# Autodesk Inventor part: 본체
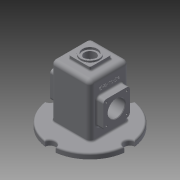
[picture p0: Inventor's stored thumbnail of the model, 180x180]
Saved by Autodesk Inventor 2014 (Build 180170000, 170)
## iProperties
Created: 2018-07
Part Number: 본체
Material: Generic
Document SubType Name: Modeling
Designer: kh
Density: 1 g/cm^3
Appearance: Default
Author: kh
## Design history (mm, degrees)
sketch "Sketch1"
  geometry: L1 (-75, 0)-(75, 0); L2 (0, -75)-(0, 75); C1 r 10 at (75, 0); C2 r 10 at (0, 75); C3 r 10 at (-75, 0); C4 r 10 at (0, -75); A1 r 75 centre (0, 0) between (-75, 0) and (75, 0); 1 further point
  constraints: 5 centre point, 5 coincident, 4 end point, 4 point on circle, 1 horizontal, 1 perpendicular
  dimensions: "d0" = 150 diameter of A1; "d2" = 150 distance of L1.start L1.end; "d3" = 150 distance of L2.start L2.end; "d4" = 20 diameter of C1; "d5" = 20 diameter of C2; "d6" = 20 diameter of C3; "d7" = 20 diameter of C4
extrude "Extrusion1" new body sketch "Sketch1" distance "d8" = 10; taper "d9" = 0 deg
extrude "Extrusion2" cut sketch "Sketch1" distance "d10" = 10; taper "d11" = 0 deg
sketch "Sketch2"
  geometry: L1 (-37, -37)-(37, -37); L2 (37, -37)-(37, 37); L3 (37, 37)-(-37, 37); L4 (-37, 37)-(-37, -37); L5 (-37, -37)-(37, 37); L6 (37, -37)-(-37, 37); 1 further point
  constraints: 12 end point, 2 midpoint, 2 parallel, 1 horizontal, 1 perpendicular
  dimensions: "d12" = 74 distance of L3.end L2.end; "d13" = 74 distance of L2.end L1.end
extrude "Extrusion3" join sketch "Sketch2" distance "d14" = 100; taper "d15" = 0 deg
sketch "Sketch3"
  geometry: L1 (-37, -37)-(37, -37) reference; L2 (37, -37)-(37, 37) reference; L3 (37, 37)-(-37, 37) reference; L4 (-37, 37)-(-37, -37) reference; L5 (-20, -20)-(20, -20); L6 (20, -20)-(20, 20); L7 (20, 20)-(-20, 20); L8 (-20, 20)-(-20, -20); L9 (-20, -20)-(20, 20); L10 (20, -20)-(-20, 20); 1 further point
  constraints: 12 end point, 2 midpoint, 2 parallel, 1 horizontal, 1 perpendicular
  dimensions: "d16" = 40 distance of L7.end L6.end; "d17" = 40 distance of L6.end L5.end
extrude "Extrusion4" join sketch "Sketch3" distance "d18" = 7; taper "d19" = 0 deg
sketch "Sketch4"
  geometry: L1 (-20, -20)-(20, -20) reference; L2 (20, -20)-(20, 20) reference; L3 (20, 20)-(-20, 20) reference; L4 (-20, 20)-(-20, -20) reference; C1 r 17.5 at (0, 0); 1 further point
  constraints: 1 centre point, 1 coincident
  dimensions: "d20" = 35 diameter of C1
extrude "Extrusion5" join sketch "Sketch4" distance "d21" = 3; taper "d22" = 0 deg
sketch "Sketch5"
  geometry: L1 (65, 10)-(65, 0) reference; L2 (65, 0)-(-65, 0) reference; L3 (-65, 0)-(-65, 10) reference; L4 (-65, 10)-(-37, 10) reference; L5 (-37, 10)-(-37, 110) reference; L6 (-37, 110)-(-20, 110) reference; L7 (-20, 110)-(-20, 117) reference; L8 (-20, 117)-(-17.5, 117) reference; L9 (-17.5, 117)-(-17.5, 120) reference; L10 (-17.5, 120)-(17.5, 120) reference; L11 (17.5, 120)-(17.5, 117) reference; L12 (17.5, 117)-(20, 117) reference; L13 (20, 117)-(20, 110) reference; L14 (20, 110)-(37, 110) reference; L15 (37, 110)-(37, 10) reference; L16 (37, 10)-(65, 10) reference; L17 (-32, 105)-(32, 105); L18 (32, 105)-(32, 0); L19 (32, 0)-(-32, 0); L20 (-32, 0)-(-32, 105)
  constraints: 8 end point, 2 parallel, 1 horizontal, 1 perpendicular, 1 point on line
  dimensions: "d26" = 64 distance of L18.end L19.end; "d27" = 5 distance between parallel lines of L15 L18; "d29" = 5 distance between parallel lines of L17 L6
extrude "Extrusion6" cut sketch "Sketch5" stored distance "d30" = 64; taper "d31" = 0 deg
sketch "Sketch7"
  geometry: L1 (70, 62)-(20, 62); L2 (20, 62)-(20, 12); L3 (20, 12)-(70, 12); L4 (70, 12)-(70, 62); L5 (70, 37)-(20, 37); L6 (45, 12)-(45, 62); 2 further points
  constraints: 12 end point, 5 midpoint, 2 parallel, 1 horizontal, 1 horizontal alignment, 1 perpendicular
  dimensions: "d33" = 50 distance of L2.end L3.end; "d34" = 50 distance of L1.end L2.end; "d35" = 55 distance from line of point (-10, 37) L6
extrude "Extrusion7" join sketch "Sketch7" distance "d36" = 13; taper "d37" = 0 deg
mirror "Mirror1"
sketch "Sketch8"
  geometry: L1 (65, 10)-(65, 0) reference; L2 (65, 0)-(32, 0) reference; L3 (32, 0)-(32, 105) reference; L4 (32, 105)-(-32, 105) reference; L5 (-32, 105)-(-32, 0) reference; L6 (-32, 0)-(-65, 0) reference; L7 (-65, 0)-(-65, 10) reference; L8 (-65, 10)-(-37, 10) reference; L9 (-37, 10)-(-37, 30) reference; L10 (-37, 30)-(-50, 30) reference; L11 (-50, 30)-(-50, 80) reference; L12 (-50, 80)-(-37, 80) reference; L13 (-37, 80)-(-37, 110) reference; L14 (-37, 110)-(-20, 110) reference; L15 (-20, 110)-(-20, 117) reference; L16 (-20, 117)-(-17.5, 117) reference; L17 (-17.5, 117)-(-17.5, 120) reference; L18 (-17.5, 120)-(17.5, 120) reference; L19 (17.5, 120)-(17.5, 117) reference; L20 (17.5, 117)-(20, 117) reference; L21 (20, 117)-(20, 110) reference; L22 (20, 110)-(37, 110) reference; L23 (37, 110)-(37, 80) reference; L24 (37, 80)-(50, 80) reference; L25 (50, 80)-(50, 30) reference; L26 (50, 30)-(37, 30) reference; L27 (37, 30)-(37, 10) reference; L28 (37, 10)-(65, 10) reference; L29 (-32, 55)-(32, 55); L30 (-32, 30)-(-25, 32.548); L31 (-25, 32.548)-(-25, 55); L32 (-32, 30)-(-32, 55); 1 further point
  constraints: 8 end point, 4 point on line, 2 perpendicular, 1 collinear
  dimensions: "d38" = 55 vertical distance of point (0, 0) L29.end; "d39" = 7 distance between parallel lines of L32 L31; "d40" = 110 deg angle of L5 L30; "d41" = 50 diameter of L30.start L29
revolve "Revolution1" sketch "Sketch8" stored, may be unused: angle "d42" = 90 deg
mirror "Mirror2"
sketch "Sketch9"
  geometry: C1 r 16 at (25, 25); 1 further point
  constraints: 1 centre point, 1 horizontal alignment
  dimensions: "d43" = 32 diameter of C1; "d44" = 55 distance of C1.centre point (80, 25)
extrude "Extrusion8" cut sketch "Sketch9" stored distance "d45" = 13; taper "d46" = 0 deg
sketch "Sketch10"
  geometry: C1 r 17.5 at (0, 0) reference; 1 further point
hole "Hole1" sketch "Sketch10" at (0, 0) diameter "d47" = 21; stored, may be unused: countersink angle "d51" = 90 deg, drill point angle "d53" = 0 deg; dims "d48" = 6, "d49" = 28, "d50" = 4, "d52" = 8
fillet "Fillet1" dims "d54" = 8
fillet "Fillet2" dims "d55" = 3
fillet "Fillet5" dims "d58" = 6
fillet "Fillet6" dims "d59" = 6
sketch "Sketch11"
  geometry: L1 (50, 38)-(50, 0) reference; L2 (44, -6)-(6, -6) reference; L3 (0, 0)-(0, 38) reference; L4 (6, 44)-(44, 44) reference; L5 (70, -32.807)-(70, 70.807) reference; L6 (73, 74.902)-(80, 74.902) reference; L7 (80, 74.902)-(80, -36.902) reference; L8 (80, -36.902)-(73, -36.902) reference; C1 r 16 at (25, 19) reference; A1 r 6 centre (44, 38) between (50, 38) and (44, 44) reference; A2 r 6 centre (44, 0) between (44, -6) and (50, 0) reference; A3 r 6 centre (6, 0) between (0, 0) and (6, -6) reference; A4 r 6 centre (6, 38) between (6, 44) and (0, 38) reference; 1 further point
  constraints: 2 other
hole "Hole2" sketch "Sketch11" at (6, 0), (44, 0), (44, 38), (6, 38) diameter "d60" = 3.242; stored, may be unused: countersink angle "d64" = 90 deg, drill point angle "d66" = 118 deg; dims "d61" = 8, "d62" = 28, "d63" = 4, "d65" = 10
sketch "Sketch12"
  geometry: L1 (26, 62)-(64, 62) reference; L2 (70, 56)-(70, 18) reference; L3 (64, 12)-(26, 12) reference; L4 (20, 18)-(20, 56) reference; L5 (0, 88.807)-(0, -14.807) reference; L6 (-3, -18.902)-(-10, -18.902) reference; L7 (-10, -18.902)-(-10, 92.902) reference; L8 (-10, 92.902)-(-3, 92.902) reference; C1 r 16 at (45, 37) reference; A1 r 6 centre (26, 56) between (26, 62) and (20, 56) reference; A2 r 6 centre (64, 56) between (70, 56) and (64, 62) reference; A3 r 6 centre (64, 18) between (64, 12) and (70, 18) reference; A4 r 6 centre (26, 18) between (20, 18) and (26, 12) reference; 1 further point
  constraints: 2 other
hole "Hole3" sketch "Sketch12" at (64, 56), (26, 56), (26, 18), (64, 18) diameter "d67" = 3.242; stored, may be unused: countersink angle "d71" = 90 deg, drill point angle "d73" = 118 deg; dims "d68" = 8, "d69" = 28, "d70" = 4, "d72" = 10
fillet "Fillet7" dims "d74" = 3
chamfer "Chamfer1" distance "d76" = 1; stored, may be unused: second distance "d77" = 2, angle "d78" = 45 deg
fillet "Fillet9" dims "d79" = 3
fillet "Fillet10" dims "d84" = 8
fillet "Fillet11" dims "d85" = 3
sketch "Sketch14"
  geometry: L1 (-4.176, -5.921)-(-4.176, 63.921); L2 (-4.176, 63.921)-(28.176, 63.921); L3 (28.176, 63.921)-(28.176, -5.921); L4 (28.176, -5.921)-(-4.176, -5.921); L5 (12, -5.921)-(12, 63.921); L6 (-4.176, 29)-(28.176, 29); L7 (89, 66)-(0, 66) reference; L8 (-18, 46.5)-(-18, 11.5) reference; 1 further point
  constraints: 4 end point, 4 midpoint, 2 other
  dimensions: "d86" = 37 distance between parallel lines of L7 L6; "d87" = 30 distance between parallel lines of L8 L5
emboss "Emboss2" sketch "Sketch14" dims "d88" = 0.5, "d89" = 0
chamfer "Chamfer2" distance "d90" = 1; stored, may be unused: second distance "d91" = 2, angle "d92" = 45 deg
fillet "Fillet13" dims "d94" = 3
fillet "Fillet14" dims "d95" = 3
body "Solid1"
node "Projected Loop1"
node "Projected Loop2"
node "Project Cut Edges1"
node "Project Cut Edges3"
node "Project Cut Edges4"
node "Project Cut Edges5"
node "Project Cut Edges6"
